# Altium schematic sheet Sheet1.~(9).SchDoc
size A2; SheetNumber: 1; SheetTotal: 1
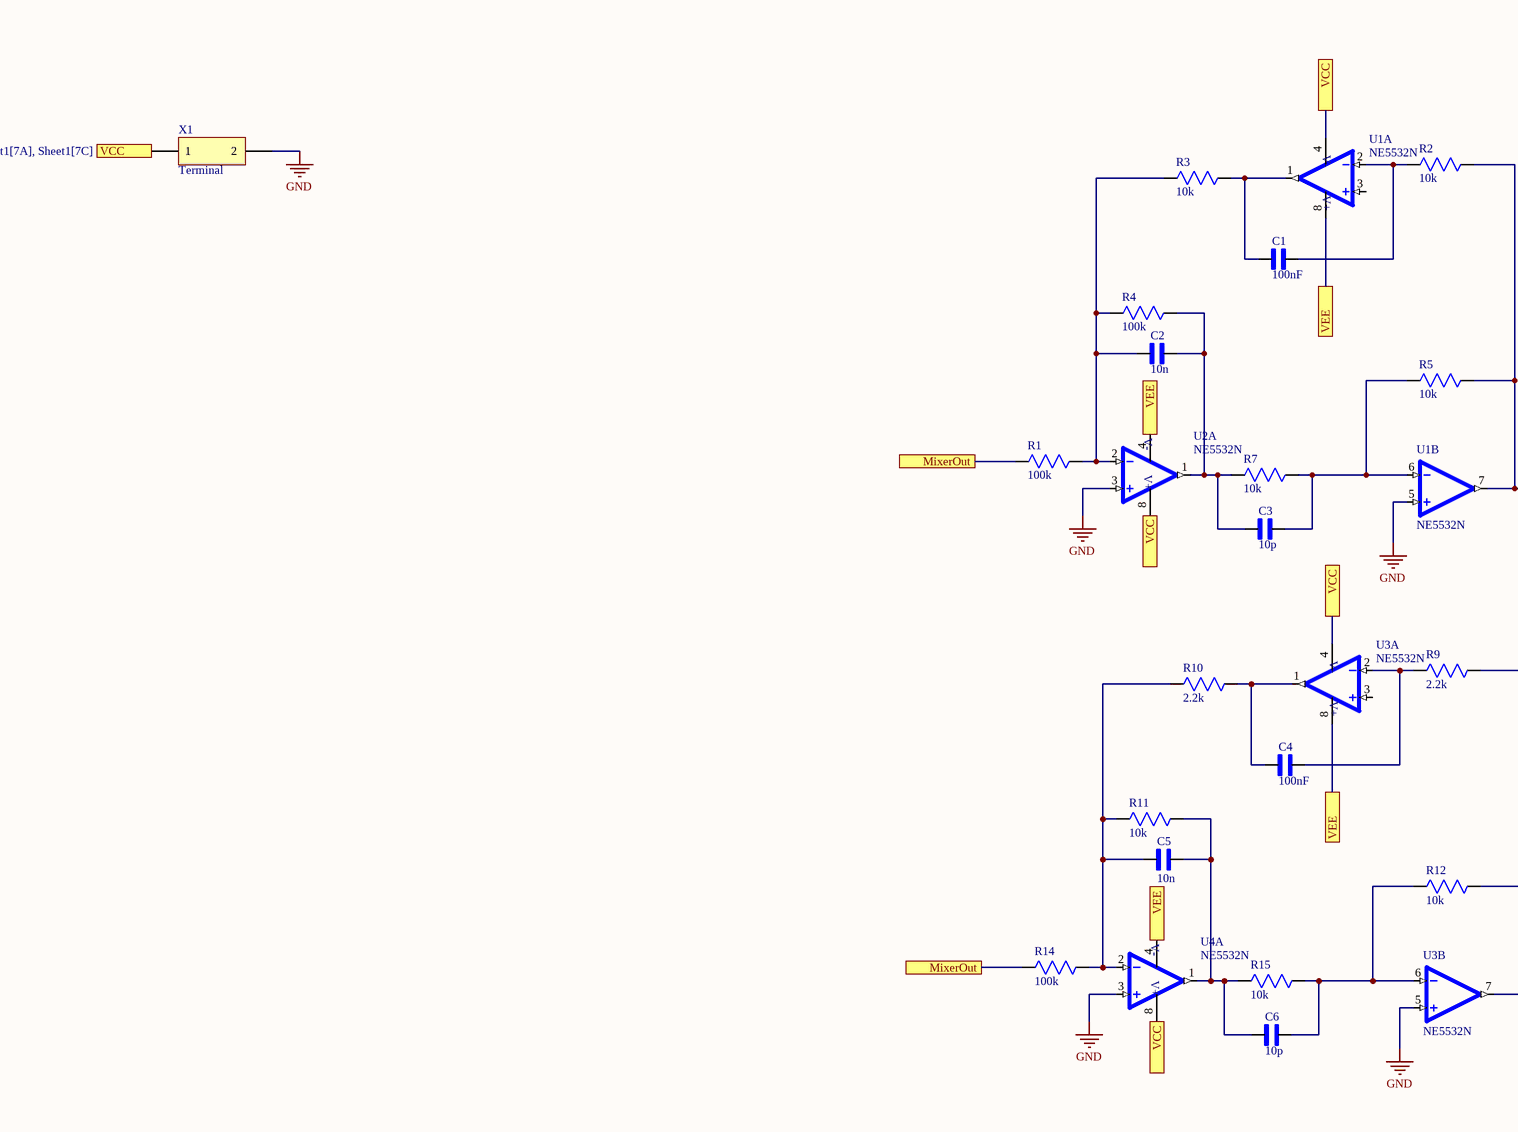
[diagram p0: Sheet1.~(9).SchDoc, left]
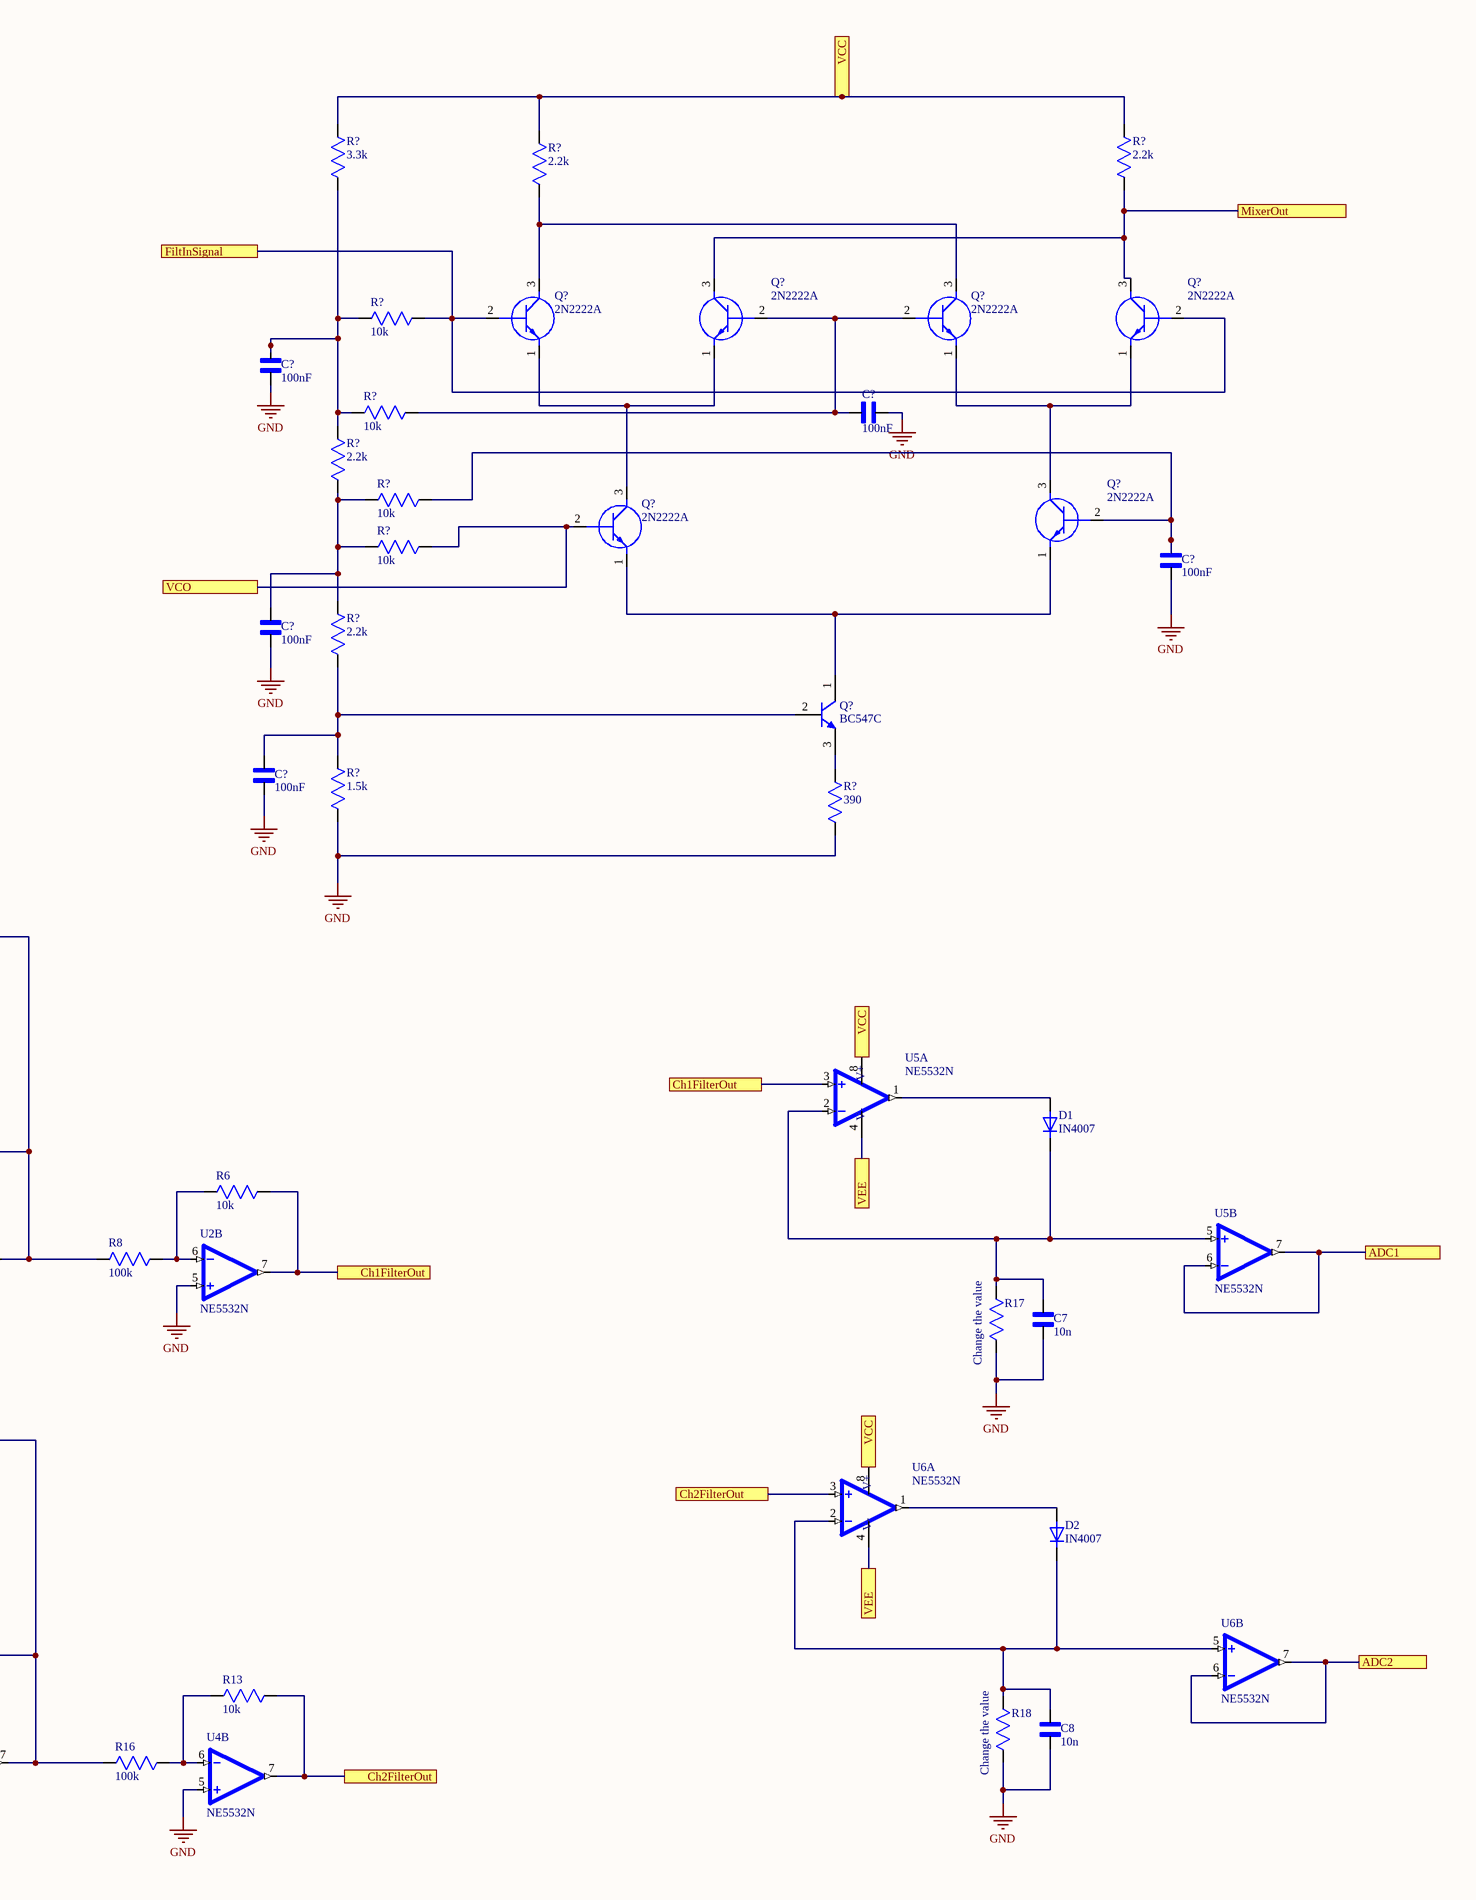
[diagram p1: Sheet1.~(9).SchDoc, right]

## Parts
(Parts that share a designator on the sheet are numbered #1, #2 ... from top to bottom, then left to right.)
C1  100nF  [CAPC2012X95N]
C2  10n  [CAPC2012X95N]
C3  10p  [CAPC2012X95N]
C4  100nF  [CAPC2012X95N]
C5  10n  [CAPC2012X95N]
C6  10p  [CAPC2012X95N]
C7  10n  [CAPC2012X95N]
C8  10n  [CAPC2012X95N]
C?#1  100nF  [CAPC2012X95N]
C?#2  100nF  [CAPC2012X95N]
C?#3  100nF  [CAPC2012X95N]
C?#4  100nF  [CAPC2012X95N]
C?#5  100nF  [CAPC2012X95N]
D1  IN4007  [DIOAD1070W78L470D235P]
D2  IN4007  [DIOAD1070W78L470D235P]
Q?#1  2N2222A  [2N2222A]
Q?#2  2N2222A  [2N2222A]
Q?#3  2N2222A  [2N2222A]
Q?#4  2N2222A  [2N2222A]
Q?#5  2N2222A  [2N2222A]
Q?#6  2N2222A  [2N2222A]
Q?#7  BC547C  [ONSC-TO-92-3-29-11]
R1  100k  [RC0805N_YAG-M]
R2  10k  [RC0805N_YAG-M]
R3  10k  [RC0805N_YAG-M]
R4  100k  [RC0805N_YAG-M]
R5  10k  [RC0805N_YAG-M]
R6  10k  [RC0805N_YAG-M]
R7  10k  [RC0805N_YAG-M]
R8  100k  [RC0805N_YAG-M]
R9  2.2k  [RC0805N_YAG-M]
R10  2.2k  [RC0805N_YAG-M]
R11  10k  [RC0805N_YAG-M]
R12  10k  [RC0805N_YAG-M]
R13  10k  [RC0805N_YAG-M]
R14  100k  [RC0805N_YAG-M]
R15  10k  [RC0805N_YAG-M]
R16  100k  [RC0805N_YAG-M]
R17  Change the value  [RC0805N_YAG-M]
R18  Change the value  [RC0805N_YAG-M]
R?#1  3.3k  [RC0805N_YAG-M]
R?#2  2.2k  [RC0805N_YAG-M]
R?#3  2.2k  [RC0805N_YAG-M]
R?#4  10k  [RC0805N_YAG-M]
R?#5  2.2k  [RC0805N_YAG-M]
R?#6  10k  [RC0805N_YAG-M]
R?#7  10k  [RC0805N_YAG-M]
R?#8  10k  [RC0805N_YAG-M]
R?#9  2.2k  [RC0805N_YAG-M]
R?#10  1.5k  [RC0805N_YAG-M]
R?#11  390  [RC0805N_YAG-M]
U1  NE5532N  [DIP766W45P254L1016H533Q8]  (parts A,B of 2)
U2  NE5532N  [DIP766W45P254L1016H533Q8]  (parts A,B of 2)
U3  NE5532N  [DIP766W45P254L1016H533Q8]  (parts A,B of 2)
U4  NE5532N  [DIP766W45P254L1016H533Q8]  (parts A,B of 2)
U5  NE5532N  [DIP766W45P254L1016H533Q8]  (parts A,B of 2)
U6  NE5532N  [DIP766W45P254L1016H533Q8]  (parts A,B of 2)
X1  Terminal  [CON_TERMINAL_2POL]

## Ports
ADC1, ADC2, Ch1FilterOut (see Sheet1[5C]), Ch1FilterOut (see Sheet1[6C]), Ch2FilterOut (see Sheet1[5D]), Ch2FilterOut (see Sheet1[6C]), FiltInSignal, MixerOut (see Sheet1[3C], Sheet1[3D]), MixerOut (see Sheet1[3C], Sheet1[8A]), MixerOut (see Sheet1[3D], Sheet1[8A]), VCC (see Sheet1[1B], Sheet1[3C], Sheet1[3D], Sheet1[4B], Sheet1[4C], Sheet1[7A], Sheet1[7C]), VCC (see Sheet1[1B], Sheet1[3C], Sheet1[3D], Sheet1[4B], Sheet1[4C], Sheet1[7C]), VCC (see Sheet1[1B], Sheet1[3C], Sheet1[3D], Sheet1[4B], Sheet1[7A], Sheet1[7C]), VCC (see Sheet1[1B], Sheet1[3C], Sheet1[3D], Sheet1[4C], Sheet1[7A], Sheet1[7C]), VCC (see Sheet1[1B], Sheet1[3C], Sheet1[4B], Sheet1[4C], Sheet1[7A], Sheet1[7C]), VCC (see Sheet1[1B], Sheet1[3D], Sheet1[4B], Sheet1[4C], Sheet1[7A], Sheet1[7C]), VCC (see Sheet1[3C], Sheet1[3D], Sheet1[4B], Sheet1[4C], Sheet1[7A], Sheet1[7C]), VCO, VEE (see Sheet1[3C], Sheet1[3D], Sheet1[4C], Sheet1[4D], Sheet1[7C]), VEE (see Sheet1[3C], Sheet1[3D], Sheet1[4C], Sheet1[4D], Sheet1[7D]), VEE (see Sheet1[3C], Sheet1[3D], Sheet1[4C], Sheet1[7C], Sheet1[7D]), VEE (see Sheet1[3C], Sheet1[3D], Sheet1[4D], Sheet1[7C], Sheet1[7D]), VEE (see Sheet1[3C], Sheet1[4C], Sheet1[4D], Sheet1[7C], Sheet1[7D]), VEE (see Sheet1[3D], Sheet1[4C], Sheet1[4D], Sheet1[7C], Sheet1[7D])

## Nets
GND: C7.2 C8.2 C?#1.2 C?#2.1 C?#3.1 C?#4.2 C?#5.2 R17.1 R18.1 R?#10.1 R?#11.1 U1.5(+INB) U2.3(+INA) U2.5(+INB) U3.5(+INB) U4.3(+INA) U4.5(+INB) X1.2
ADC1: U5.6(-INB) U5.7(OUTB) ; port ADC1
ADC2: U6.6(-INB) U6.7(OUTB) ; port ADC2
Ch1FilterOut: R6.1 U2.7(OUTB) U5.3(+INA) ; port Ch1FilterOut
Ch2FilterOut: R13.1 U4.7(OUTB) U6.3(+INA) ; port Ch2FilterOut
FiltInSignal: Q?#1.2(B) Q?#4.2(B) R?#4.2 ; port FiltInSignal
MixerOut: Q?#2.3(C) Q?#4.3(C) R1.2 R14.2 R?#2.1 ; port MixerOut
VCC: R?#1.2 R?#2.2 R?#3.2 U1.4(V-) U2.8(V+) U3.4(V-) U4.8(V+) U5.8(V+) U6.8(V+) X1.1 ; port VCC
VCO: Q?#6.2(B) R?#8.2 ; port VCO
VEE: U1.8(V+) U2.4(V-) U3.8(V+) U4.4(V-) U5.4(V-) U6.4(V-) ; port VEE
NetC1_1: C1.1 R3.1 U1.1(OUTA)
NetC1_2: C1.2 R2.2 U1.2(-INA)
NetC2_1: C2.1 R1.1 R3.2 R4.2 U2.2(-INA)
NetC2_2: C2.2 C3.1 R4.1 R7.2 U2.1(OUTA)
NetC3_2: C3.2 R5.2 R7.1 U1.6(-INB)
NetC4_1: C4.1 R10.1 U3.1(OUTA)
NetC4_2: C4.2 R9.2 U3.2(-INA)
NetC5_1: C5.1 R10.2 R11.2 R14.1 U4.2(-INA)
NetC5_2: C5.2 C6.1 R11.1 R15.2 U4.1(OUTA)
NetC6_2: C6.2 R12.2 R15.1 U3.6(-INB)
NetC7_1: C7.1 D1.C R17.2 U5.2(-INA) U5.5(+INB)
NetC8_1: C8.1 D2.C R18.2 U6.2(-INA) U6.5(+INB)
NetC?#1_1: C?#1.1 R?#1.1 R?#4.1 R?#5.2 R?#6.1
NetC?#2_2: C?#2.2 Q?#2.2(B) Q?#3.2(B) R?#6.2
NetC?#3_2: C?#3.2 Q?#5.2(B) R?#7.2
NetC?#4_1: C?#4.1 R?#5.1 R?#7.1 R?#8.1 R?#9.2
NetC?#5_1: C?#5.1 Q?#7.2(B) R?#9.1 R?#10.2
NetD1_A: D1.A U5.1(OUTA)
NetD2_A: D2.A U6.1(OUTA)
NetQ?#1_1: Q?#1.1(E) Q?#2.1(E) Q?#6.3(C)
NetQ?#1_3: Q?#1.3(C) Q?#3.3(C) R?#3.1
NetQ?#3_1: Q?#3.1(E) Q?#4.1(E) Q?#5.3(C)
NetQ?#5_1: Q?#5.1(E) Q?#6.1(E) Q?#7.1(C)
NetQ?#7_3: Q?#7.3(E) R?#11.2
NetR2_1: R2.1 R5.1 R8.2 U1.7(OUTB)
NetR6_2: R6.2 R8.1 U2.6(-INB)
NetR9_1: R9.1 R12.1 R16.2 U3.7(OUTB)
NetR13_2: R13.2 R16.1 U4.6(-INB)

Not connected (* = marked no-connect by the designer): U1 3(+INA); U3 3(+INA)

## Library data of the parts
C1 C4 C?#1-C?#5 = CAP_0805_GENERIC: 0.1 ÂµF Â±10% 50V Ceramic Capacitor X7R 0805 (2012 Metric); MF: Samsung Electro-Mechanics; MP: CL21B104KBCNNNC
C2 C3 C5-C8 = CAP_0805_GENERIC: 0.1 ÂµF Â±10% 50V Ceramic Capacitor X7R 0805 (2012 Metric); Value: 100nF; MF: Samsung Electro-Mechanics; MP: CL21B104KBCNNNC
D1 D2 = IN4007: Diode Standard 1000 V 1A Through Hole DO-204AL (DO-41); MF: Vishay Semiconductor
Q?#1-Q?#6 = 2N2222A: Transistor BJT NPN; Manufacturer_Name: Diotec
Q?#7 = ONSC-NPN-C1B2E3-3: Amplifier Transistor, NPN Silicon, 3-Pin TO-92, Bulk Box; Manufacturer: On Semiconductor; IC Continuous (A): 0.1; fT Min (MHz): 150
R1 R4 R8-R10 R14 R16-R18 R?#1-R?#3 R?#5 R?#9-R?#11 = RES_0805_GENERIC_1: Description; Manufacturer_Name: Yageo; Manufacturer_Part_Number: RC0805FR-0710KL; Value: 10k
R2 R3 R5-R7 R11-R13 R15 R?#4 R?#6-R?#8 = RES_0805_GENERIC_1: Description; Manufacturer_Name: Yageo; Manufacturer_Part_Number: RC0805FR-0710KL
U1-U6 = NE5532N: IC, OP AMP, DUAL; No. of Amplifiers: 2 Amplifier; Bandwidth: 10MHz; Slew Rate: 8V/Âµs; Supply Voltage Range: Â± 15V; Amplifier Case Style: DIP; No. of Pins: 8Pins; Operating Temperature Min: 0Â°C; Operating Temperature Max: 70Â°C; MSL: -; SVHC: No SVHC (1; MF: Fairchild Semiconductor
X1 = CON_TERMINAL_2POL: Terminal Screw; Manufacturer_Name: Yageo; Manufacturer_Part_Number: RC0805FR-0710KL; Value: 10k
